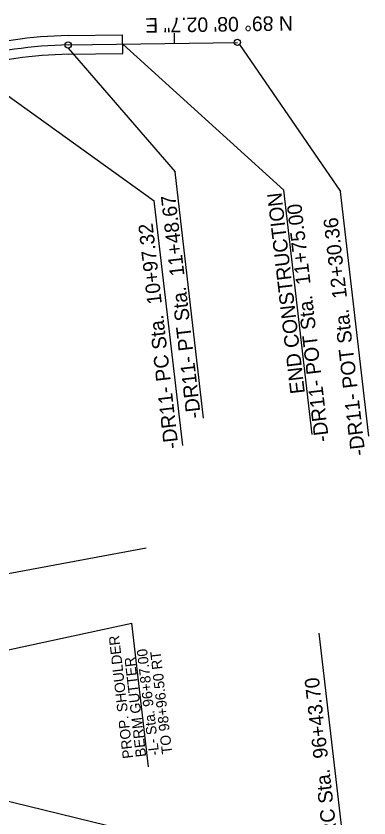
# Model space of a CAD drawing. Extents: x 472216 to 481979, y 489069 to 507339.
# Drawn here: x 478323.6 to 478493.9, y 496242.1 to 496629.2 of the extents above; entities that cross this region are included whole.
import ezdxf

# ---------------------------------------------------------------- set-up
doc = ezdxf.new("R2010")
doc.units = 0
for name, color, linetype in [('Old_Level_12', 7, 'Continuous'), ('Prop Drainage Structure Pipe CSP 15in', 7, 'Continuous'), ('Prop Drainage Structure Pipe RCP 24in Class III Label', 7, 'Continuous'), ('Sheet Block Revision CELL', 7, 'Continuous'), ('Sheet Block Title CELL', 7, 'Continuous'), ('Sheet North Arrow Point CELL', 7, 'Continuous'), ('Sheet PE Seal Cell', 7, 'Continuous'), ('Sheet Plan And Profile CELL', 7, 'Continuous')]:
    doc.layers.add(name, color=color, linetype=linetype)

msp = doc.modelspace()

# ---------------------------------------------------------------- linework, layer by layer
at = {"layer": 'Old_Level_12'}
for p, q in [((478375.06, 496615.66), (478452.76, 496545.2)), ((478431.47, 496615.44), (478480.12, 496544.46)), ((478348.75, 496613.77), (478400.34, 496553.98)), ((478297.93, 496606.35), (478390.25, 496539.95)), ((478414.05, 496435.1), (478400.34, 496553.98)), ((478466.56, 496427.21), (478452.76, 496545.2)), ((478493.91, 496426.47), (478480.12, 496544.46)), ((478404.04, 496421.95), (478390.25, 496539.95)), ((478484.05, 496210.14), (478469.89, 496331.34)), ((478256.32, 496265.71), (478484.05, 496210.14))]:
    msp.add_line(p, q, dxfattribs=at)
for centre in [(478348.73, 496615.27), (478430.41, 496616.5)]:
    msp.add_circle(centre, 1.5, dxfattribs=at)
at = {"layer": 'Prop Drainage Structure Pipe RCP 24in Class III Label'}
for p, q in [((478348.66, 496619.77), (478374.99, 496620.16)), ((478375.13, 496611.16), (478374.99, 496620.16)), ((478348.8, 496610.77), (478375.13, 496611.16))]:
    msp.add_line(p, q, dxfattribs=at)
for radius in [204.5, 195.5]:
    msp.add_arc((478351.75, 496415.29), radius, 90.8659, 105.7331, dxfattribs=at)
at = {"layer": 'Sheet Block Revision CELL'}
for p in [(478265.7, 496311.71), (478387.43, 496266.69)]:
    msp.add_line(p, (478379.43, 496336.07), dxfattribs=at)
at = {"layer": 'Sheet Block Title CELL'}
msp.add_line((478091.43, 496317.69), (478386.38, 496372.54), dxfattribs=at)
at = {"layer": 'Sheet North Arrow Point CELL'}
msp.add_line((478348.73, 496615.27), (478430.41, 496616.5), dxfattribs=at)
msp.add_arc((478351.75, 496415.29), 200, 90.8659, 105.7331, dxfattribs=at)
at = {"layer": 'Sheet PE Seal Cell'}
msp.add_line((478400.06, 496616.04), (478399.98, 496621.04), dxfattribs=at)

# ---------------------------------------------------------------- texts
at = {"layer": 'Old_Level_12'}
for s, rotation, p in [('-DR11- PT Sta.  11+48.67', 96.5773, (478412.83, 496435.31)), ('END CONSTRUCTION ', 96.6671, (478463.01, 496447.22)), ('-DR11- POT Sta.  11+75.00', 96.6671, (478474.66, 496423.95)), ('-DR11- POT Sta.  12+30.36', 96.6671, (478492.23, 496417.32)), ('-DR11- PC Sta.  10+97.32', 96.5773, (478402.02, 496420.66)), ('-L- PRC Sta.  96+43.70', 96.5773, (478480.87, 496213.32))]:
    msp.add_text(s, height=7, rotation=rotation, dxfattribs=at).set_placement(p)
at = {"layer": 'Prop Drainage Structure Pipe CSP 15in'}
for s, p in [('PROP. SHOULDER ', (478380.12, 496271)), ('-L- Sta. 96+87.00', (478392.71, 496272.46)), ('TO 98+96.50 RT', (478399.01, 496273.18)), ('BERM GUTTER', (478386.41, 496271.73))]:
    msp.add_text(s, height=5, rotation=96.5773, dxfattribs=at).set_placement(p)
at = {"layer": 'Sheet Plan And Profile CELL'}
msp.add_text('N 89%%d 08\' 02.7" E', height=7, rotation=180.8659, dxfattribs=at).set_placement((478457.15, 496629.25))

doc.saveas('drawing.dxf')
